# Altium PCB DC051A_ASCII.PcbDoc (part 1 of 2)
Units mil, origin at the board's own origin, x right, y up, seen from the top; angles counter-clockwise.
Board outline 3200 x 2600 mil, 4 copper layers (L1-TOP, L2-GND, L3-POWER, L4-BOTTOM), stack 58.217 mil thick; 95 components, 55 nets, 249 pads, 164 vias.
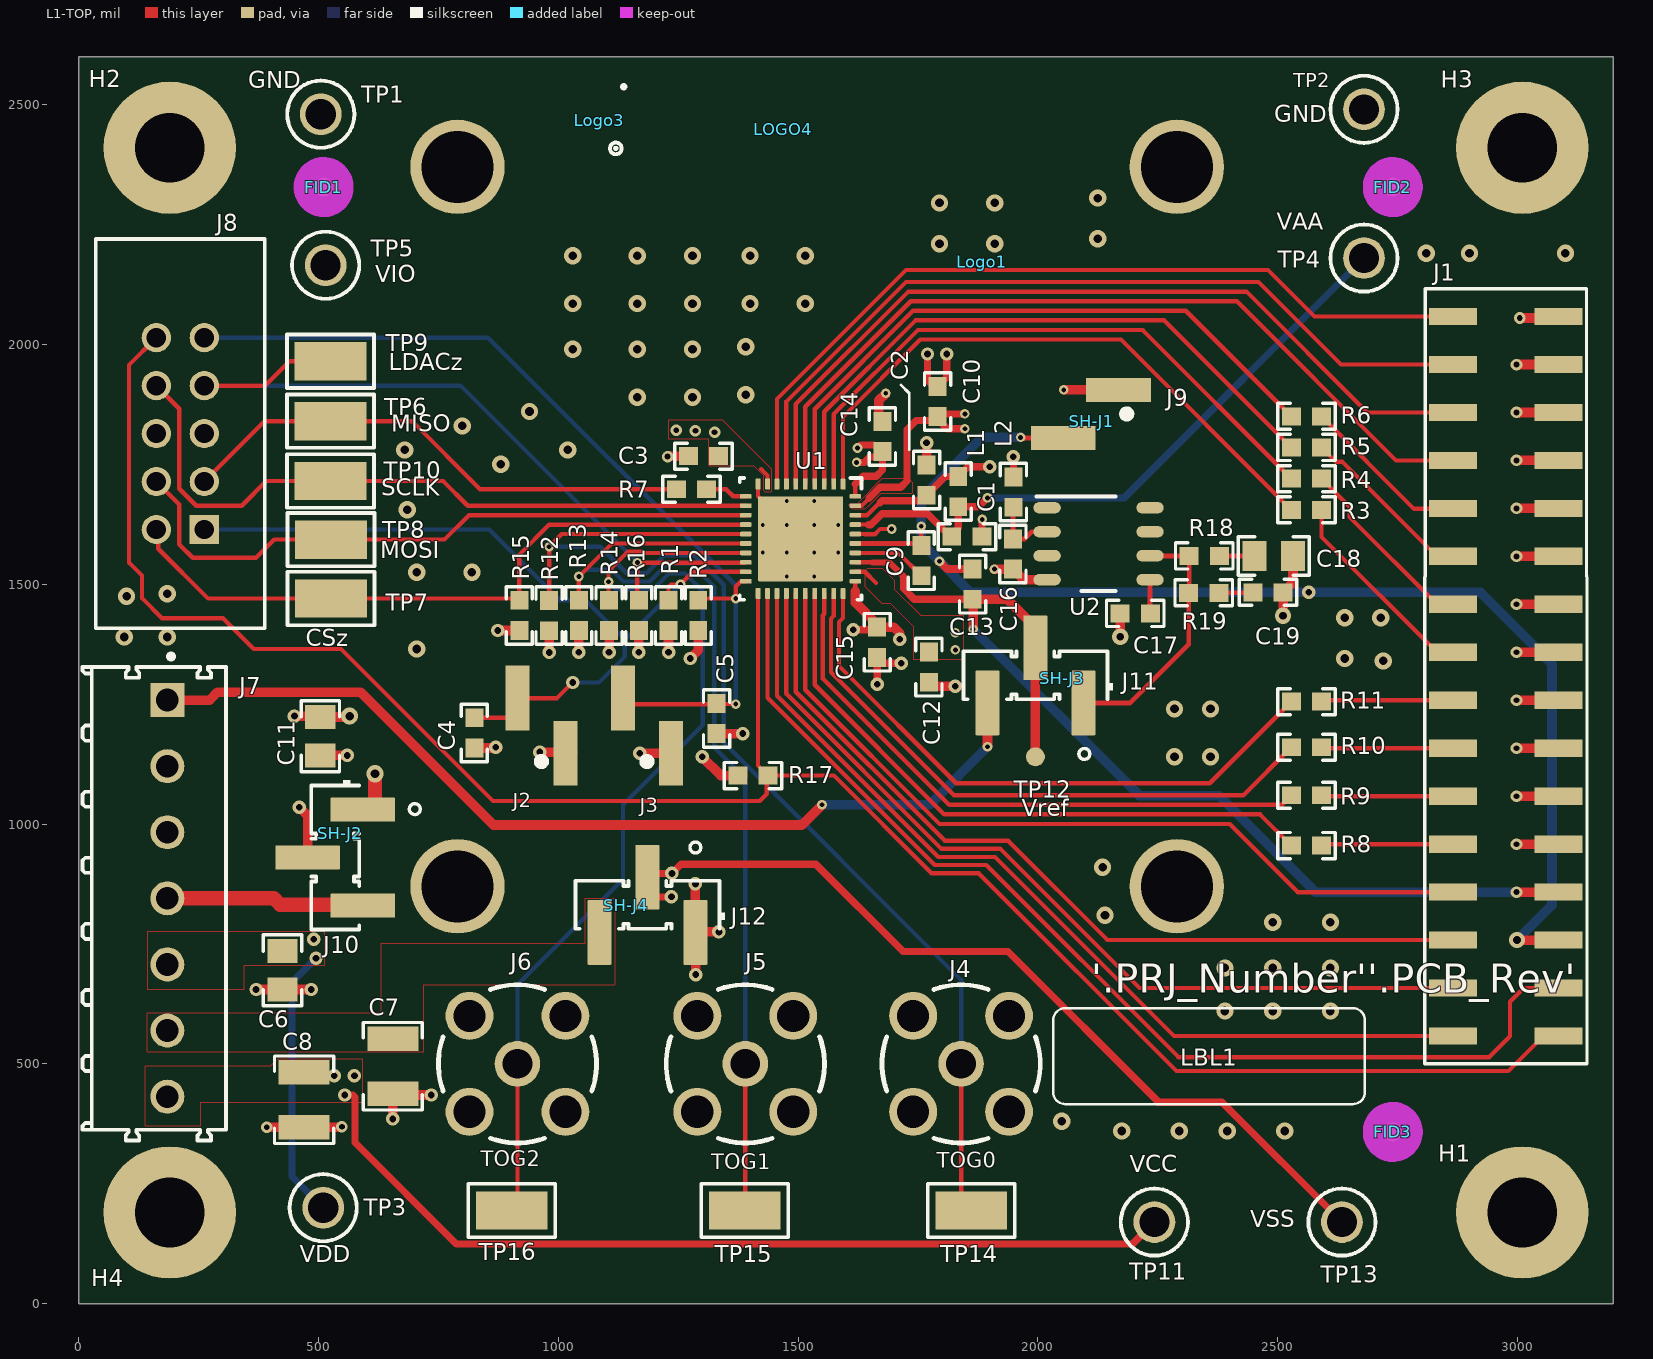
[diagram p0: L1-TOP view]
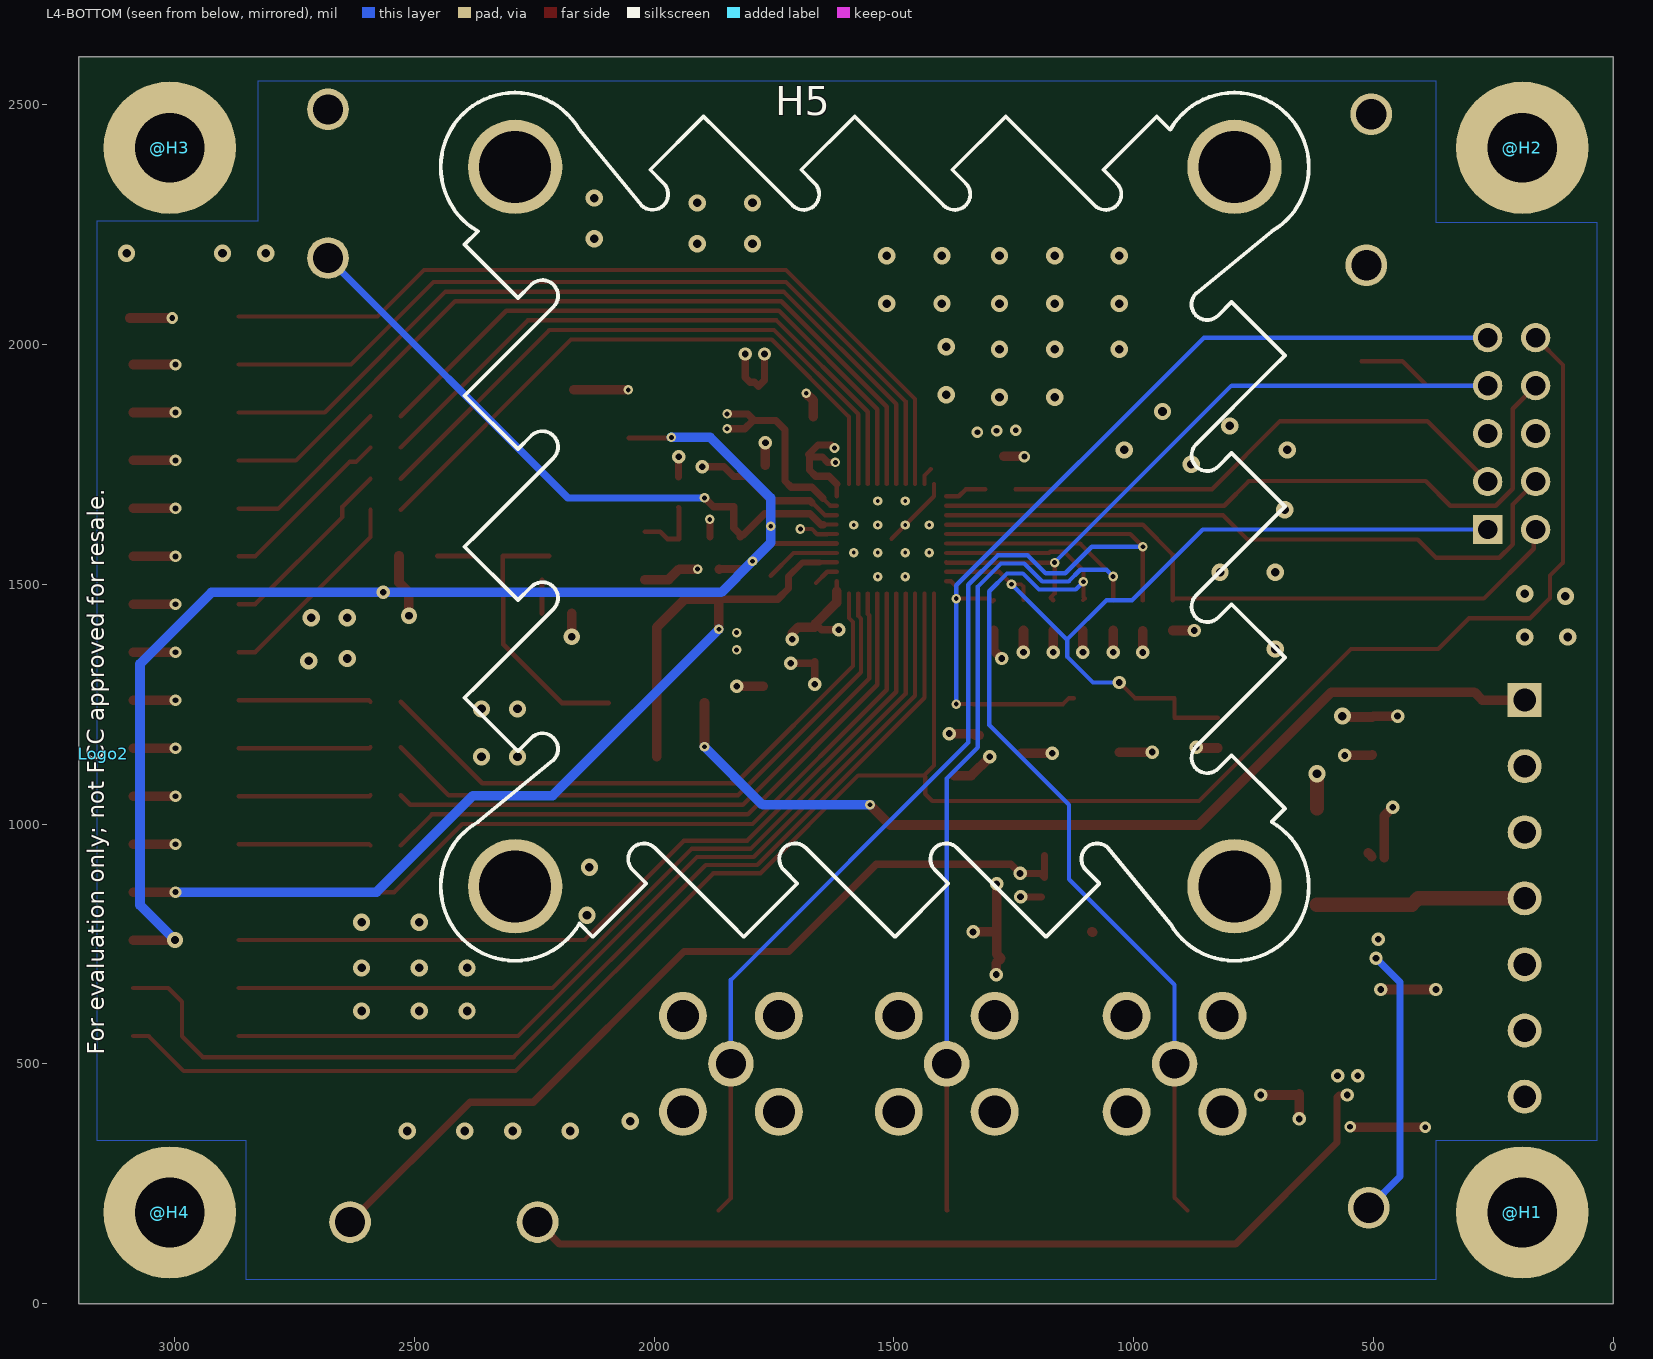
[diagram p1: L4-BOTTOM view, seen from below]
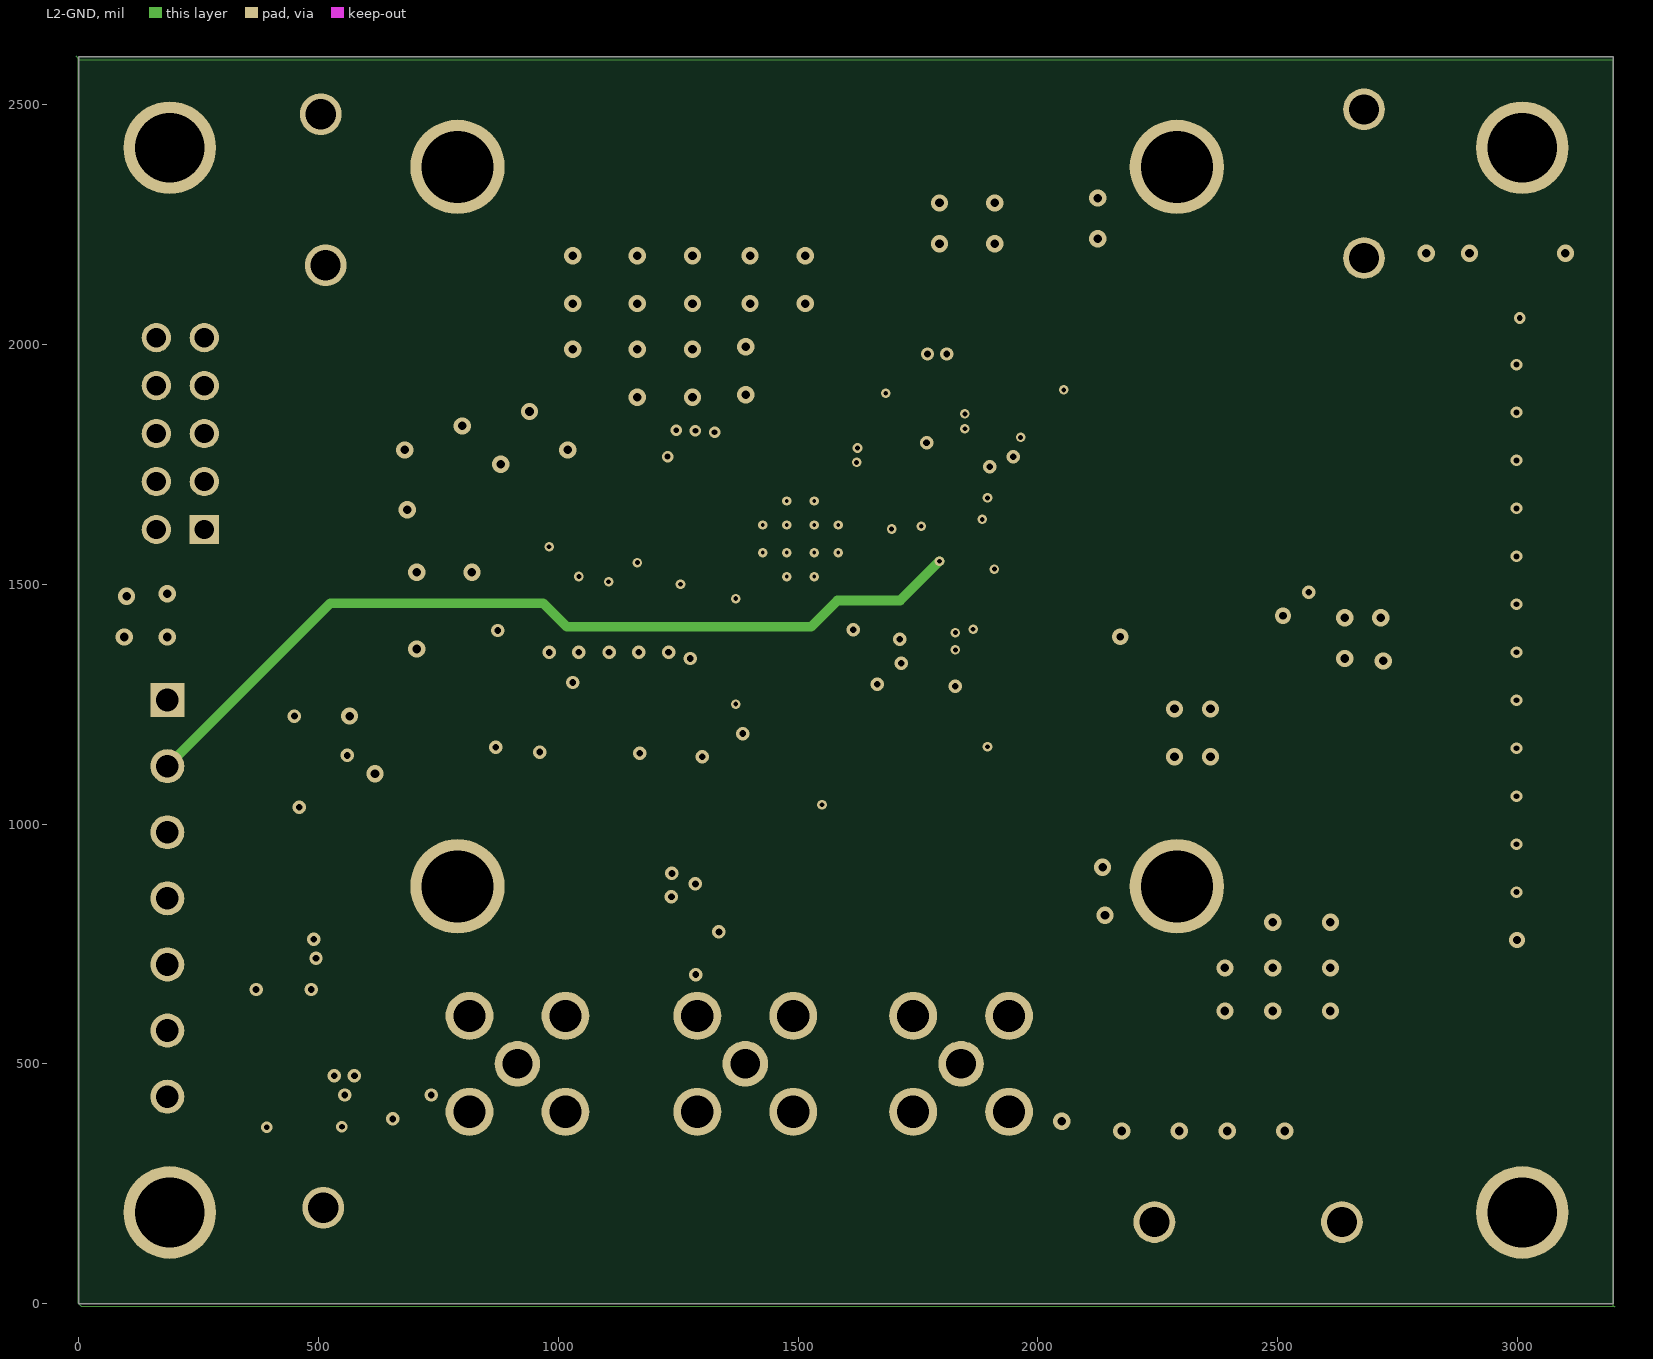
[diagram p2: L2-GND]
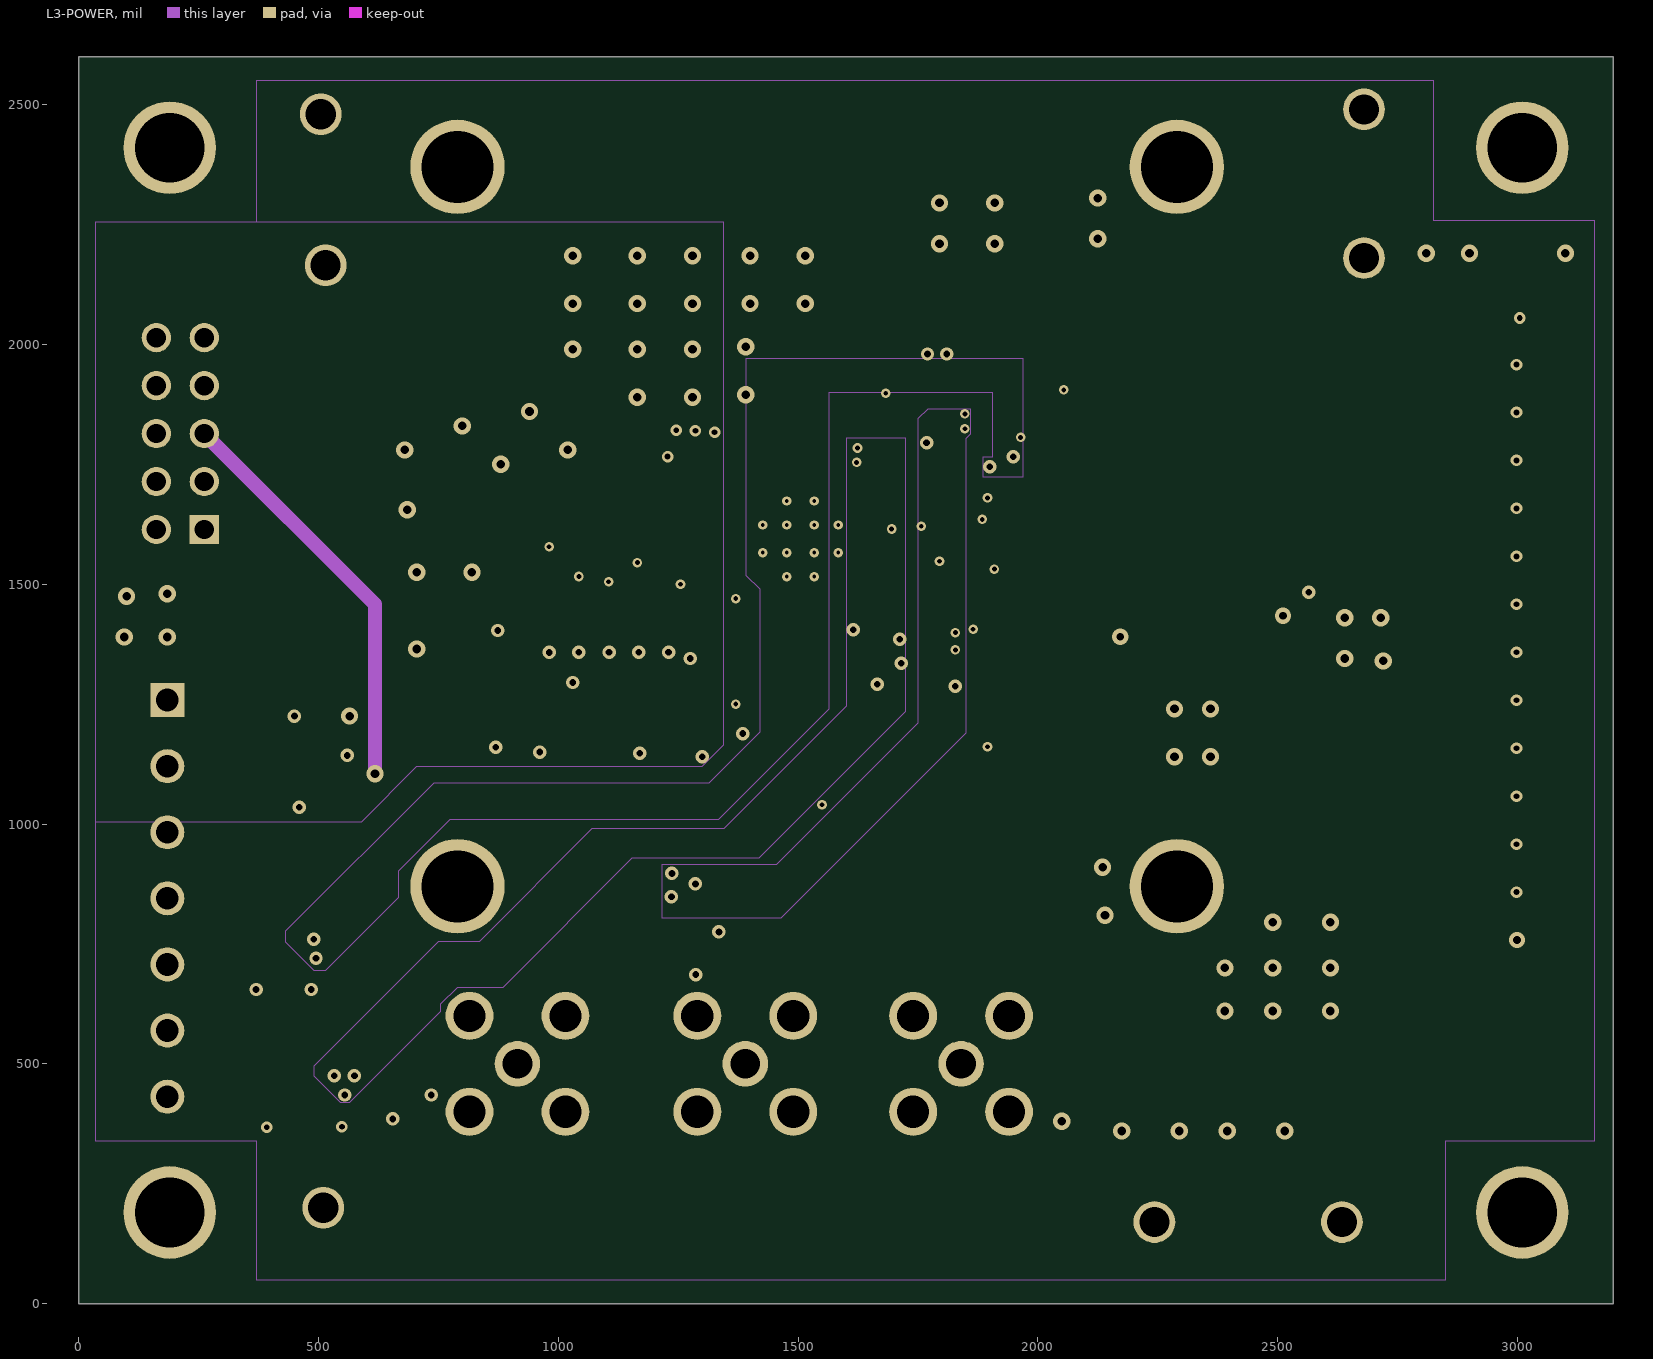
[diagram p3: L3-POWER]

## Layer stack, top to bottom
Top Solder: solder mask 0.4, Solder Resist, Dk 3.5
L1-TOP: signal copper 1.4
Dielectric1: core 10, FR-406, Dk 4.6
L2-GND: signal copper 1.417
Dielectric2: prepreg 32.6, FR-4, Dk 4.8
L3-POWER: signal copper 1.4
Dielectric3: core 10, FR-406, Dk 4.6
L4-BOTTOM: signal copper 1.4
Bottom Solder: solder mask 0.4, Solder Resist, Dk 3.5

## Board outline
0,0 0,2600 3200,2600 3200,0

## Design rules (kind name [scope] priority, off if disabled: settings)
AcuteAngle [All] p0: scope1count=1 scope1_0_kind=Board scope1_0_value=Board scope2count=1 scope2_0_kind=Board scope2_0_value=Board commentlength=0 minimum=4.50000000000000E+0001
AcuteAngle [All] p1: minimum=4.50000000000000E+0001 checktracksonly=FALSE
AssemblyTestPointUsage [All] p0: scope1count=1 scope1_0_kind=Board scope1_0_value=Board scope2count=1 scope2_0_kind=Board scope2_0_value=Board commentlength=0
AssemblyTestPointUsage [All] p1: valid=2
AssemblyTestpoint [All] p0: scope1count=1 scope1_0_kind=Board scope1_0_value=Board scope2count=1 scope2_0_kind=Board scope2_0_value=Board commentlength=0
BoardOutlineClearance [All] p0 off: scope1count=1 scope1_0_kind=Board scope1_0_value=Board scope2count=1 scope2_0_kind=Board scope2_0_value=Board commentlength=172 gap=40 // Protel DXP Scope 1 Expression Was: OnCopper and Not InComponentClass('Logo') and not InComponentClass('FiducialMark') and not InRegion(1000,500,4000,800) and not InPoly
BoardOutlineClearance BoardOutlineClearance_Poly [All] p0 off: scope1count=1 scope1_0_kind=Board scope1_0_value=Board scope2count=1 scope2_0_kind=Board scope2_0_value=Board commentlength=58 gap=25 // Protel DXP Scope 1 Expression Was: OnCopper and IsPoly
BoardOutlineClearance BoardOutlineClearance_MountingHoles [All] p0 off: scope1count=1 scope1_0_kind=Board scope1_0_value=Board scope2count=1 scope2_0_kind=Board scope2_0_value=Board commentlength=86 gap=40 // Protel DXP Scope 1 Expression Was: OnCopper and InComponentClass('Mounting Holes')
BoardOutlineClearance BoardOutlineClearance_MountingHoles [OnCopper and InComponentClass('Mounting Holes')] p1: gap=40 ignorepadtopadclearanceinfootprint=FALSE
BoardOutlineClearance BoardOutlineClearance_Poly [OnCopper and IsPoly] p2: gap=25 ignorepadtopadclearanceinfootprint=FALSE
BoardOutlineClearance [OnCopper and Not InComponentClass('Logo') and not InComponentClass('FiducialMark') and not InRegion(1000,500,4000,800) and not InPoly] p3: gap=40 ignorepadtopadclearanceinfootprint=FALSE
Clearance [All] p0: scope1count=1 scope1_0_kind=Board scope1_0_value=Board scope2count=1 scope2_0_kind=Board scope2_0_value=Board commentlength=0 gap=7.87
Clearance Clearance_Poly [All] p0 off: scope1count=1 scope1_0_kind=Board scope1_0_value=Board scope2count=1 scope2_0_kind=Board scope2_0_value=Board commentlength=48 gap=25 // Protel DXP Scope 1 Expression Was: InPolygon
Clearance Clearance_Keepouts [All] p0 off: scope1count=1 scope1_0_kind=Board scope1_0_value=Board scope2count=1 scope2_0_kind=Board scope2_0_value=Board commentlength=99 gap=0 // Protel DXP Scope 2 Expression Was: ((IsTrack Or IsArc) And Not InPoly) And IsFree and IsKeepOut
Clearance Clearance_Keepouts [((IsTrack Or IsArc) And Not InPoly) And IsFree and IsKeepOut vs ((IsTrack Or IsArc) And Not InPoly) And IsFree and IsKeepOut] p1: gap=0 ignorepadtopadclearanceinfootprint=FALSE
Clearance Clearance_Poly [InPolygon] p2: gap=25 ignorepadtopadclearanceinfootprint=FALSE except(0: Arc-Hole Track-Hole SMDPad-Hole THPad-Hole Via-Hole Fill-Hole Poly-Hole Region-Hole Text-Hole; 10: Poly-Poly; 15: Track-Poly SMDPad-Poly Via-Poly)
Clearance [All] p3: gap=7.87 ignorepadtopadclearanceinfootprint=FALSE except(0: Arc-SMDPad Arc-Hole Track-Hole SMDPad-Hole THPad-Hole Via-Hole Fill-Hole Poly-Hole Region-Hole Text-Hole)
ComponentClearance [All] p0: scope1count=1 scope1_0_kind=Board scope1_0_value=Board scope2count=1 scope2_0_kind=Board scope2_0_value=Board commentlength=0 gap=0 collisioncheckmode=3
ComponentClearance ComponentClearance_THtoTH [All] p0 off: scope1count=1 scope1_0_kind=Board scope1_0_value=Board scope2count=1 scope2_0_kind=Board scope2_0_value=Board commentlength=54 gap=30 collisioncheckmode=3 // Protel DXP Scope 2 Expression Was: IsThruComponent
ComponentClearance ComponentClearance_THtoSMT [All] p0 off: scope1count=1 scope1_0_kind=Board scope1_0_value=Board scope2count=1 scope2_0_kind=Board scope2_0_value=Board commentlength=53 gap=0 collisioncheckmode=3 // Protel DXP Scope 2 Expression Was: IsSMTComponent
ComponentClearance ComponentClearance_SmallPassives [All] p0 off: scope1count=1 scope1_0_kind=Board scope1_0_value=Board scope2count=1 scope2_0_kind=Board scope2_0_value=Board commentlength=542 gap=14.96 collisioncheckmode=3 // Protel DXP Scope 2 Expression Was: HasFootprint('0201*') or HasFootprint('0402*') or HasFootprint('0508') or HasFootprint('0603*') or HasFootprint('0612') or HasFootprint('0805*') or HasFootprint('0815*') or HasFootprint('0830*') or HasFootprint('1206*') or HasFootprint('1210*') or HasFootprint('1808*') or HasFootprint('1812*') or HasFootprint('1825*') or HasFootprint('2010*') or HasFootprint('2220*') or HasFootprint('2225*') or HasFootprint('2512*') or HasFootprint('2728*') or HasFootprint('3518*') or HasFootprint('Keystone_1902C')
ComponentClearance ComponentClearance_MountingHoles [All] p0: scope1count=1 scope1_0_kind=ComponentClass scope1_0_value="Mounting Holes" scope2count=1 scope2_0_kind=Board scope2_0_value=Board commentlength=0 gap=0 collisioncheckmode=3
ComponentClearance ComponentClearance_ScrewToNut [All] p0 off: scope1count=1 scope1_0_kind=Board scope1_0_value=Board scope2count=1 scope2_0_kind=Board scope2_0_value=Board commentlength=71 gap=0 collisioncheckmode=3 // Protel DXP Scope 2 Expression Was: (HasFootprint('Keystone_1902C'))
ComponentClearance ComponentClearance_Logo [All] p0: scope1count=1 scope1_0_kind=ComponentClass scope1_0_value=Logo scope2count=1 scope2_0_kind=Board scope2_0_value=Board commentlength=0 gap=40 collisioncheckmode=3
ComponentClearance ComponentClearance_Shunt [All] p0: scope1count=1 scope1_0_kind=ComponentClass scope1_0_value=Header scope2count=1 scope2_0_kind=ComponentClass scope2_0_value=Shunt commentlength=0 gap=0 collisioncheckmode=3
ComponentClearance ComponentClearance_MountingHoles_FiducialMarks [All] p0: scope1count=1 scope1_0_kind=ComponentClass scope1_0_value="Mounting Holes" scope2count=1 scope2_0_kind=ComponentClass scope2_0_value=FiducialMark commentlength=0 gap=0 collisioncheckmode=3
ComponentClearance ComponentClearance_MountingHoles_FiducialMarks [InComponentClass('Mounting Holes') vs InComponentClass('FiducialMark')] p1: gap=0 collisioncheckmode=3 verticalgap=10 showdistances=FALSE
ComponentClearance ComponentClearance_Shunt [InComponentClass('Header') vs InComponentClass('Shunt')] p2: gap=0 collisioncheckmode=3 verticalgap=0 showdistances=FALSE
ComponentClearance ComponentClearance_Logo [InComponentClass('Logo')] p3: gap=40 collisioncheckmode=3 verticalgap=10 showdistances=FALSE
ComponentClearance ComponentClearance_ScrewToNut [(HasFootprint('NY PMS 440 0025 PH')) vs (HasFootprint('Keystone_1902C'))] p4: gap=0 collisioncheckmode=3 verticalgap=0 showdistances=FALSE
ComponentClearance ComponentClearance_MountingHoles [InComponentClass('Mounting Holes')] p5: gap=0 collisioncheckmode=3 verticalgap=100000 showdistances=FALSE
ComponentClearance ComponentClearance_SmallPassives [HasFootprint('0201*') or HasFootprint('0402*') or HasFootprint('0508') or HasFootprint('0603*') or HasFootprint('0612') or HasFootprint('0805*') or HasFootprint('0815*') or HasFootprint('0830*') or HasFootprint('1206*') or HasFootprint('1210*') or HasFootprint('1808*') or HasFootprint('1812*') or HasFootprint('1825*') or HasFootprint('2010*') or HasFootprint('2220*') or HasFootprint('2225*') or HasFootprint('2512*') or HasFootprint('2728*') or HasFootprint('3518*') or HasFootprint('NY PMS 440 0025 PH') vs HasFootprint('0201*') or HasFootprint('0402*') or HasFootprint('0508') or HasFootprint('0603*') or HasFootprint('0612') or HasFootprint('0805*') or HasFootprint('0815*') or HasFootprint('0830*') or HasFootprint('1206*') or HasFootprint('1210*') or HasFootprint('1808*') or HasFootprint('1812*') or HasFootprint('1825*') or HasFootprint('2010*') or HasFootprint('2220*') or HasFootprint('2225*') or HasFootprint('2512*') or HasFootprint('2728*') or HasFootprint('3518*') or HasFootprint('Keystone_1902C')] p6: gap=14.96 collisioncheckmode=3 verticalgap=10 showdistances=FALSE
ComponentClearance ComponentClearance_THtoSMT [IsThruComponent vs IsSMTComponent] p7: gap=0 collisioncheckmode=3 verticalgap=0 showdistances=FALSE
ComponentClearance ComponentClearance_THtoTH [IsThruComponent vs IsThruComponent] p8: gap=30 collisioncheckmode=3 verticalgap=30 showdistances=FALSE
ComponentClearance [All] p9: gap=0 collisioncheckmode=3 verticalgap=10 showdistances=FALSE
DiffPairsRouting [All] p0: scope1count=1 scope1_0_kind=Board scope1_0_value=Board scope2count=1 scope2_0_kind=Board scope2_0_value=Board commentlength=0
DiffPairsRouting [All] p1: maxlimit=100 minlimit=10 mostfreqgap=10 toplayer_minwidth=15 toplayer_maxwidth=15 toplayer_prefwidth=15 midlayer1_minwidth=15 midlayer1_maxwidth=15 midlayer1_prefwidth=15 midlayer2_minwidth=15 midlayer2_maxwidth=15 midlayer2_prefwidth=15 bottomlayer_minwidth=15 bottomlayer_maxwidth=15 bottomlayer_prefwidth=15 maxuncoupledlength=1000
FabricationTestPointUsage TestPointUsage [All] p0: scope1count=1 scope1_0_kind=Board scope1_0_value=Board scope2count=1 scope2_0_kind=Board scope2_0_value=Board commentlength=0 valid=2 allowmultiple=FALSE
FabricationTestPointUsage TestPointUsage [All] p1: valid=2 allowmultiple=FALSE
FabricationTestpoint Testpoint [All] p0: scope1count=1 scope1_0_kind=Board scope1_0_value=Board scope2count=1 scope2_0_kind=Board scope2_0_value=Board commentlength=0 side=3 testpointundercomponent=TRUE minsize=40 maxsize=100 preferedsize=60 minholesize=0 maxholesize=40 preferedholesize=32 testpointgrid=1
FabricationTestpoint Testpoint [All] p1: side=3 testpointundercomponent=TRUE minsize=40 maxsize=100 preferedsize=60 minholesize=0 maxholesize=40 preferedholesize=32 testpointgrid=1 allowsidetop=TRUE allowsidebottom=TRUE usegrid=TRUE gridtolerance=0.01
FanoutControl Fanout_Small [All] p0 off: scope1count=1 scope1_0_kind=Board scope1_0_value=Board scope2count=1 scope2_0_kind=Board scope2_0_value=Board commentlength=84 // Protel DXP Scope 1 Expression Was: (CompPinCount < 5)   Fanout_Small (Default Rule)
FanoutControl Fanout_Default [All] p0: scope1count=1 scope1_0_kind=Board scope1_0_value=Board scope2count=1 scope2_0_kind=Board scope2_0_value=Board commentlength=30 // Fanout_Default (Default Rule)
FanoutControl Fanout_SOIC [All] p0 off: scope1count=1 scope1_0_kind=Board scope1_0_value=Board scope2count=1 scope2_0_kind=Board scope2_0_value=Board commentlength=71 // Protel DXP Scope 1 Expression Was: IsSOIC   Fanout_SOIC (Default Rule)
FanoutControl Fanout_BGA [All] p0 off: scope1count=1 scope1_0_kind=Board scope1_0_value=Board scope2count=1 scope2_0_kind=Board scope2_0_value=Board commentlength=69 // Protel DXP Scope 1 Expression Was: IsBGA   Fanout_BGA (Default Rule)
FanoutControl Fanout_LCC [All] p0 off: scope1count=1 scope1_0_kind=Board scope1_0_value=Board scope2count=1 scope2_0_kind=Board scope2_0_value=Board commentlength=69 // Protel DXP Scope 1 Expression Was: IsLCC   Fanout_LCC (Default Rule)
FanoutControl Fanout_LCC [IsLCC] p1: bgadir=Out bgaviamode=Centered fanoutstyle=Auto fanoutdirection=Alternating viagrid=1 // Fanout_LCC (Default Rule)
FanoutControl Fanout_BGA [IsBGA] p2: bgadir=Out bgaviamode=Centered fanoutstyle=Auto fanoutdirection=Alternating viagrid=1 // Fanout_BGA (Default Rule)
FanoutControl Fanout_Default [All] p4: bgadir=Out bgaviamode=Centered fanoutstyle=Auto fanoutdirection=Alternating viagrid=1 // Fanout_Default (Default Rule)
FanoutControl Fanout_Small [(CompPinCount < 5)] p5: bgadir=Out bgaviamode=Centered fanoutstyle=Auto fanoutdirection=OutThenIn viagrid=1 // Fanout_Small (Default Rule)
Height [All] p0: scope1count=1 scope1_0_kind=Board scope1_0_value=Board scope2count=1 scope2_0_kind=Board scope2_0_value=Board commentlength=0
Height [All] p1: minheight=0 maxheight=1400 prefheight=500
HoleSize [All] p0: scope1count=1 scope1_0_kind=Board scope1_0_value=Board scope2count=1 scope2_0_kind=Board scope2_0_value=Board commentlength=0 absolutevalues=TRUE maxlimit=251 minlimit=7.87 maxpercent=80.000 minpercent=20.000
HoleSize [All] p1: absolutevalues=TRUE maxlimit=251 minlimit=7.87 maxpercent=80.000 minpercent=20.000
HoleToHoleClearance [All] p0: scope1count=1 scope1_0_kind=Board scope1_0_value=Board scope2count=1 scope2_0_kind=Board scope2_0_value=Board commentlength=0
LayerPairs [All] p0: scope1count=1 scope1_0_kind=Board scope1_0_value=Board scope2count=1 scope2_0_kind=Board scope2_0_value=Board commentlength=0 enforce=TRUE
MinimumAnnularRing [All] p0: scope1count=1 scope1_0_kind=Board scope1_0_value=Board scope2count=1 scope2_0_kind=Board scope2_0_value=Board commentlength=0 minimumring=4
MinimumAnnularRing MinimumAnnularRing_ThermalPadVias [All] p0 off: scope1count=1 scope1_0_kind=Board scope1_0_value=Board scope2count=1 scope2_0_kind=Board scope2_0_value=Board commentlength=63 minimumring=5.91 // Protel DXP Scope 1 Expression Was: IsVia and InAnyComponent
MinimumAnnularRing MinimumAnnularRing_ThermalPadVias [IsVia and InAnyComponent] p1: minimumring=5.91
MinimumAnnularRing [All] p2: minimumring=4
MinimumSolderMaskSliver [All] p0: scope1count=1 scope1_0_kind=Board scope1_0_value=Board scope2count=1 scope2_0_kind=Board scope2_0_value=Board commentlength=0
MinimumSolderMaskSliver MinimumSolderMaskSliver_Logo [All] p0: scope1count=1 scope1_0_kind=ComponentClass scope1_0_value=Logo scope2count=1 scope2_0_kind=ComponentClass scope2_0_value=Logo commentlength=0
MinimumSolderMaskSliver MinimumSolderMaskSliver_Logo [InComponentClass('Logo') vs InComponentClass('Logo')] p1: minsoldermaskwidth=0.7
MinimumSolderMaskSliver [All] p2: minsoldermaskwidth=3.94
NetAntennae [All] p0: scope1count=1 scope1_0_kind=Board scope1_0_value=Board scope2count=1 scope2_0_kind=Board scope2_0_value=Board commentlength=0
PasteMaskExpansion [All] p0: scope1count=1 scope1_0_kind=Board scope1_0_value=Board scope2count=1 scope2_0_kind=Board scope2_0_value=Board commentlength=0 expansion=0
PlaneClearance [All] p0: scope1count=1 scope1_0_kind=Board scope1_0_value=Board scope2count=1 scope2_0_kind=Board scope2_0_value=Board commentlength=0 clearance=20
PlaneConnect [All] p0: scope1count=1 scope1_0_kind=Board scope1_0_value=Board scope2count=1 scope2_0_kind=Board scope2_0_value=Board commentlength=0 planeconnectstyle=Relief reliefexpansion=10 reliefentries=4 reliefconductorwidth=10 reliefairgap=10
PlaneConnect [All] p1: planeconnectstyle=Relief reliefexpansion=10 reliefentries=4 reliefconductorwidth=10 reliefairgap=10
PolygonConnect [All] p0: scope1count=1 scope1_0_kind=Board scope1_0_value=Board scope2count=1 scope2_0_kind=Board scope2_0_value=Board commentlength=0 connectstyle=Direct reliefconductorwidth=10 reliefentries=4 polygonreliefangle="90 Angle"
PolygonConnect [All] p1: connectstyle=Direct reliefconductorwidth=10 reliefentries=4 polygonreliefangle="90 Angle" airgapwidth=10
RoutingCorners [All] p0: scope1count=1 scope1_0_kind=Board scope1_0_value=Board scope2count=1 scope2_0_kind=Board scope2_0_value=Board commentlength=0 cornerstyle=45-Degree minsetback=100 maxsetback=100
RoutingLayers [All] p0: scope1count=1 scope1_0_kind=Board scope1_0_value=Board scope2count=1 scope2_0_kind=Board scope2_0_value=Board commentlength=0 top layer=Automatic mid layer 1=Automatic mid layer 2=Automatic bottom layer=Automatic
RoutingPriority [All] p0: scope1count=1 scope1_0_kind=Board scope1_0_value=Board scope2count=1 scope2_0_kind=Board scope2_0_value=Board commentlength=0
RoutingTopology [All] p0: scope1count=1 scope1_0_kind=Board scope1_0_value=Board scope2count=1 scope2_0_kind=Board scope2_0_value=Board commentlength=0 topology=Shortest
RoutingVias [All] p0: scope1count=1 scope1_0_kind=Board scope1_0_value=Board scope2count=1 scope2_0_kind=Board scope2_0_value=Board commentlength=0 holewidth=16 width=34 viastyle="Through Hole" minholewidth=7.87 minwidth=20 maxholewidth=40 maxwidth=65
RoutingVias ThermalPadVias [All] p0 off: scope1count=1 scope1_0_kind=Board scope1_0_value=Board scope2count=1 scope2_0_kind=Board scope2_0_value=Board commentlength=63 holewidth=7.87 width=19.68 viastyle="Through Hole" minholewidth=7.87 minwidth=19.68 maxholewidth=12.99 maxwidth=23.62 // Protel DXP Scope 1 Expression Was: IsVia and InAnyComponent
RoutingVias ThermalPadVias [IsVia and InAnyComponent] p1: holewidth=7.87 width=19.68 viastyle="Through Hole" minholewidth=7.87 minwidth=19.68 maxholewidth=12.99 maxwidth=23.62
RoutingVias [All] p2: holewidth=16 width=34 viastyle="Through Hole" minholewidth=7.87 minwidth=20 maxholewidth=40 maxwidth=65
ShortCircuit [All] p0: scope1count=1 scope1_0_kind=Board scope1_0_value=Board scope2count=1 scope2_0_kind=Board scope2_0_value=Board commentlength=0 allowed=FALSE
SilkToBoardRegionClearance [All] p0 off: scope1count=1 scope1_0_kind=Board scope1_0_value=Board scope2count=1 scope2_0_kind=Board scope2_0_value=Board commentlength=130 // Protel DXP Scope 1 Expression Was: Not ((IsComment or IsDesignator) And (Hide <> 'False')) and not InRegion(1000,500,4000,800)
SilkToBoardRegionClearance [Not ((IsComment or IsDesignator) And (Hide <> 'False')) and not InRegion(1000,500,4000,800)] p1:
SilkToSilkClearance [All] p0: scope1count=1 scope1_0_kind=Board scope1_0_value=Board scope2count=1 scope2_0_kind=Board scope2_0_value=Board commentlength=0
SilkToSilkClearance SilkToSilkClearance_Pb-FreeLogo [All] p0 off: scope1count=1 scope1_0_kind=Board scope1_0_value=Board scope2count=1 scope2_0_kind=Board scope2_0_value=Board commentlength=120 // Protel DXP Scope 2 Expression Was: (HasFootprint('Pb-Free_Overlay_Medium') OR HasFootprint('Pb-Free_Overlay_Small'))
SilkToSilkClearance SilkToSilkClearance_Pb-FreeLogo [(HasFootprint('Pb-Free_Overlay_Medium') OR HasFootprint('Pb-Free_Overlay_Small')) vs (HasFootprint('Pb-Free_Overlay_Medium') OR HasFootprint('Pb-Free_Overlay_Small'))] p1: silktosilkclearance=0
SilkToSilkClearance [All] p2: silktosilkclearance=3
SilkToSolderMaskClearance "Silk to Solder Mask Opening" [All] p0: scope1count=1 scope1_0_kind=Board scope1_0_value=Board scope2count=1 scope2_0_kind=Board scope2_0_value=Board commentlength=0
SilkToSolderMaskClearance SilkToComponentPadClearance [All] p0 off: scope1count=1 scope1_0_kind=Board scope1_0_value=Board scope2count=1 scope2_0_kind=Board scope2_0_value=Board commentlength=87 // Protel DXP Scope 1 Expression Was: (IsPad or IsFill or IsRegion) and InAnycomponent
SilkToSolderMaskClearance SilkToComponentPadClearance [(IsPad or IsFill or IsRegion) and InAnycomponent] p1: minsilkscreentomaskgap=3 clearancetoexposedcopper=TRUE
SilkToSolderMaskClearance "Silk to Solder Mask Opening" [All] p2: minsilkscreentomaskgap=3 clearancetoexposedcopper=FALSE
SolderMaskExpansion [All] p0: scope1count=1 scope1_0_kind=Board scope1_0_value=Board scope2count=1 scope2_0_kind=Board scope2_0_value=Board commentlength=0 expansion=1.97
SolderMaskExpansion [All] p1: expansion=1.97
UnRoutedNet [All] p0: scope1count=1 scope1_0_kind=Board scope1_0_value=Board scope2count=1 scope2_0_kind=Board scope2_0_value=Board commentlength=0
UnpouredPolygon [All] p0: scope1count=1 scope1_0_kind=Board scope1_0_value=Board scope2count=1 scope2_0_kind=Board scope2_0_value=Board commentlength=0
Width [All] p0: scope1count=1 scope1_0_kind=Board scope1_0_value=Board scope2count=1 scope2_0_kind=Board scope2_0_value=Board commentlength=0 maxlimit=100 minlimit=6 preferedwidth=10
Width [All] p1: maxlimit=100 minlimit=6 preferedwidth=10 checkconnectedcopper=TRUE
14 further rules are at their usual default settings.

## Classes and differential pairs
component class Shunt: SH-J1 SH-J2 SH-J3 SH-J4
component class FiducialMark: FID1 FID2 FID3
component class AssemblyNote: ZZ1 ZZ2 ZZ3 ZZ4
component class Header: J1 J2 J3 J9 J10 J11 J12
component class Logo: Logo1
component class DC051A: C1 C2 C3 C4 C5 C6 C7 C8 C9 C10 C11 C12 C13 C14 C15 C16 C17 C18 C19 GND J1 J2 J3 J4 J5 J6 J7 J8 J9 J10 J11 J12 L1 L2 R1 R2 R3 R4 R5 R6 R7 R8 R9 R10 R11 R12 R13 R14 R15 R16 R17 R18 R19 TP1 TP2 TP3 TP4 TP5 TP6 TP7 TP8 TP9 TP10 TP11 TP12 TP13 TP14 TP15 TP16 U1 U2
component class DC051A_EVM_Hardware: !PCB @H1 @H2 @H3 @H4 FID1 FID2 FID3 H1 H2 H3 H4 H5 LBL1 Logo1 Logo2 Logo3 LOGO4 Logo4 LOGO? Logo? SH-J1 SH-J2 SH-J3 SH-J4 ZZ1 ZZ2 ZZ3 ZZ4
component class Label: LBL1

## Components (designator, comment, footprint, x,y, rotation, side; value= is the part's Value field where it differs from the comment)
@H1 "1891" Keystone_1891 190,190 r180 bottom
@H2 "1891" Keystone_1891 190,2410 r180 bottom
@H3 "1891" Keystone_1891 3010,2410 r180 bottom
@H4 "1891" Keystone_1891 3010,190 r180 bottom
C1 "C0603C105K4PACTU" 0603 1852,1599 r0 top
C2 "C0603C104J4RACTU" 0603 1768,1717 r90 top
C3 "C0603C104J4RACTU" 0603 1303,1767 r180 top
C4 "C0603C105K4PACTU" 0603 825,1190 r270 top
C5 "C0603C105K4PACTU" 0603 1330,1220 r270 top
C6 "GRM21BC8YA106KE11L" 0805_HV 425,695 r270 top
C7 "UMJ325KB7106KMHT" 1210_270 655,495 r270 top
C8 "UMJ325KB7106KMHT" 1210_270 470,425 r270 top
C9 "C0603C102K5RACTU" 0603 1757,1549 r90 top
C10 "C0603C105K4PACTU" 0603 1791,1881 r90 top
C11 "GRM21BC8YA106KE11L" 0805_HV 504,1183 r90 top
C12 "C0603C105K4PACTU" 0603 1773,1327 r270 top
C13 "C0603C104J4RACTU" 0603 1864,1500 r90 top
C14 "C0603C105K4PACTU" 0603 1676,1808 r90 top
C15 "C0603C105K4PACTU" 0603 1665,1379 r270 top
C16 "C1608X5R1E105K080AC" 0603 1948,1563 r270 top
C17 "C1608X5R1E105K080AC" 0603 2203,1439 r180 top
C18 "GRM21BC8YA106KE11L" 0805_HV 2492,1559 r0 top
C19 "C1608X5R1E105K080AC" 0603 2480,1483 r0 top
FID1 "Fiducial" Fiducial10-30 511,2328 r180 top
FID2 "Fiducial" Fiducial10-30 2740,2328 r180 top
FID3 "Fiducial" Fiducial10-30 2740,358 r180 top
H1 "29311" Keystone29311 3010,190 r0 top
H2 "29311" Keystone29311 190,2410 r0 top
H3 "29311" Keystone29311 3010,2410 r0 top
H4 "29311" Keystone29311 190,190 r0 top
H5 "500403B00000G" Aavid_500403B00000G 1540,1620 r0 bottom
J1 "TSM-116-01-T-DV-P" CONN_TSM-116-01-T-DV-P 2976,1308 r90 top
J2 "TSM-102-01-L-SV" Samtec_TSM-102-01-L-SV 965,1205 r180 top
J3 "TSM-102-01-L-SV" Samtec_TSM-102-01-L-SV 1185,1205 r180 top
J4 "142-0701-231" Johnson_142-0701-231 1840,500 r270 top
J5 "142-0701-231" Johnson_142-0701-231 1389.99,500 r180 top
J6 "142-0701-231" Johnson_142-0701-231 915,500 r90 top
J7 "1984662" Phoenix_1984662 185,845 r270 top locked
J8 "AWHW-10G-0202-T" Assman_AWHW-10G-0x02-T 212,1814 r180 top
J9 "TSM-102-01-L-SV" Samtec_TSM-102-01-L-SV 2110.52,1855 r270 top
J10 "TSM-103-01-L-SV-P-TR" Samtec_TSM-103-01-x-SV-P 535,930 r270 top
J11 "TSM-103-01-L-SV-P-TR" Samtec_TSM-103-01-x-SV-P 1995,1310 r180 top
J12 "TSM-103-01-L-SV-P-TR" Samtec_TSM-103-01-x-SV-P 1186,831.5 r180 top
L1 "742792651" 0603 1834,1693 r270 top
L2 "742792651" 0603 1949,1692 r270 top
LBL1 "THT-14-423-10" Label_650x200 2357,516 r0 top
Logo1 "Texas Instruments" TI_Stacked_Overlay_Medium 1883,2172 r0 top
Logo2 "FCC disclaimer" FCC_disclaimer 3149,1146 r90 bottom
Logo3 "WEEE logo" WEEE_Minimum 1086,2467 r0 top
LOGO4 "CE Mark" CE_Mark_5mm 1469,2449 r0 top
R1 "RC0603FR-0710KL" 0603 1230,1435 r270 top
R2 "RC0603FR-0710KL" 0603 1292,1435 r270 top
R3 "RC0603JR-070RL" 0603 2560,1655 r0 top
R4 "RC0603JR-070RL" 0603 2560,1720 r0 top
R5 "RC0603JR-070RL" 0603 2560,1785 r0 top
R6 "RC0603JR-070RL" 0603 2560,1850 r0 top
R7 "CRCW060333R0JNEA" 0603 1278,1698 r0 top
R8 "RC0603JR-070RL" 0603 2560,955 r0 top
R9 "RC0603JR-070RL" 0603 2560,1060 r0 top
R10 "RC0603JR-070RL" 0603 2560,1160 r0 top
R11 "RC0603JR-070RL" 0603 2560,1255 r0 top
R12 "RC0603FR-0710KL" 0603 981,1434.5 r90 top
R13 "RC0603FR-0710KL" 0603 1043,1435 r90 top
R14 "RC0603FR-0710KL" 0603 1106,1435 r90 top
R15 "RC0603FR-0710KL" 0603 919,1435 r90 top
R16 "RC0603FR-0710KL" 0603 1168,1435 r90 top
R17 "RC0603FR-0710KL" 0603 1406,1101 r0 top
R18 "ERJ-3RQFR51V" 0603 2347,1559 r180 top
R19 "RC0603FR-071RL" 0603 2346,1482 r180 top
SH-J1 "SNT-100-BK-G" SNT-100-BK-G 2112,1840 r90 top
SH-J2 "SNT-100-BK-G" SNT-100-BK-G 546,981 r90 top
SH-J3 "SNT-100-BK-G" SNT-100-BK-G 2051,1304 r180 top
SH-J4 "SNT-100-BK-G" SNT-100-BK-G 1142,831 r180 top
TP1 "5005" Keystone5005 505,2480 r270 top
TP2 "5005" Keystone5005 2680,2490 r270 top
TP3 "5005" Keystone5005 510,200 r180 top
TP4 "5005" Keystone5005 2680,2180 r180 top
TP5 "5005" Keystone5005 515,2165 r270 top
TP6 "5019" Keystone_5019 525,1840 r180 top
TP7 "5019" Keystone_5019 526,1470 r0 top
TP8 "5019" Keystone_5019 526,1593 r0 top
TP9 "5019" Keystone_5019 525,1965 r180 top
TP10 "5019" Keystone_5019 525,1715 r180 top
TP11 "5005" Keystone5005 2243,170 r180 top
TP12 "TP_SM_1MM" TP_SM_1MM 1995,1140 r180 top locked
TP13 "5005" Keystone5005 2634,170 r0 top
TP14 "5019" Keystone_5019 1861,194 r180 top
TP15 "5019" Keystone_5019 1389,194 r0 top
TP16 "5019" Keystone_5019 903,194 r0 top
U1 "DAC81416RHA" RHA0040H 1505.28,1594.7 r270 top
U2 "REF5025AIDR" D0008A_N 2126.65,1584.34 r0 top
ZZ1 "Install label in silkscreened box after final wash.  Text shall be 8 pt font.  Text shall be per the Label Table in the PDF schematic." AssemblyNote 218,3663 r0 top
ZZ2 "These assemblies are ESD sensitive, ESD precautions shall be observed." AssemblyNote 218,3570 r0 top
ZZ3 "These assemblies must be clean and free from flux and all contaminants. Use of no clean flux is not acceptable." AssemblyNote 218,3490 r0 top
ZZ4 "These assemblies must comply with workmanship standards IPC-A-610 Class 2, unless otherwise specified." AssemblyNote 218,3402 r0 top

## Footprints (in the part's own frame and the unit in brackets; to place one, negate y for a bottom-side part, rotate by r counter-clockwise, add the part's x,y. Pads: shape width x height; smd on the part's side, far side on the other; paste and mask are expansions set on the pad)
0603 [mm] "0603 from SM-752 data"
  rect 1x0.95 smd: 1(-0.8,0) 2(0.8,0)
  silkscreen extent -1.52,-0.69 1.52,0.69
0805_HV [mil] "0805 with 30mil clearance between pads"
  rect 50x63 smd: 1(-40,0) 2(40,0)
  silkscreen extent -74,-40 74,40
1210_270 [mm] "1210"
  rect 1.3x2.7 smd: 1(-1.45,0) 2(1.45,0)
  silkscreen extent -2.32,-1.57 2.32,1.57
Aavid_500403B00000G [mm] "Heat Sink TO-3 Aluminum"
  round 5 hole 3.81: MH1(-19.05,19.05) MH2(19.05,19.05) MH3(-19.05,-19.05) MH4(19.05,-19.05)
  silkscreen extent -22.99,-22.99 22.99,22.99
AssemblyNote [mil] "Assembly Note"
Assman_AWHW-10G-0x02-T [mm] "Header, 2.54mm, 5x2, TH"
  rect 1.55x1.55 hole 1.02: 1(-1.27,5.08)
  round 1.55 hole 1.02: 2(1.27,5.08) 3(-1.27,2.54) 4(1.27,2.54) 5(-1.27,0) 6(1.27,0) 7(-1.27,-2.54) 8(1.27,-2.54) 9(-1.27,-5.08) 10(1.27,-5.08)
  silkscreen extent -4.47,-10.31 4.47,10.31
CE_Mark_5mm [mil] "Minimum text height for CE Mark"
CONN_TSM-116-01-T-DV-P [mil] "Samtec"
  rect 36x100 smd: 1(-750,-110) 2(-750,110) 3(-650,-110) 4(-650,110) 5(-550,-110) 6(-550,110) 7(-450,-110) 8(-450,110) 9(-350,-110) 10(-350,110) 11(-250,-110) 12(-250,110) 13(-150,-110) 14(-150,110) 15(-50,-110) 16(-50,110) 17(50,-110) 18(50,110) 19(150,-110) 20(150,110) 21(250,-110) 22(250,110) 23(350,-110) 24(350,110) 25(450,-110) 26(450,110) 27(550,-110) 28(550,110) 29(650,-110) 30(650,110) 31(750,-110) 32(750,110)
  silkscreen extent -808,-169 808,169
D0008A_N [mm] "SOIC, 8-Leads, Body 4.9x3.9mm, Pitch 1.27mm, IPC Medium Density"
  oval 1.45x0.6 smd: 1(-2.725,1.905) 2(-2.725,0.635) 3(-2.725,-0.635) 4(-2.725,-1.905) 5(2.725,-1.905) 6(2.725,-0.635) 7(2.725,0.635) 8(2.725,1.905)
  silkscreen extent -3.3,-2.5 0.9,2.5
FCC_disclaimer [mil]
Fiducial10-30 [mm]
  round 1 smd mask+0: 1(0,0)
  L1-TOP keep-out circle w1.678: c0,0 r0.75
Johnson_142-0701-231 [mil] "Johnson Components recommended land pattern"
  round 95 hole 62: 1(0,0)
  round 100 hole 67: 2(100,100) 3(100,-100) 4(-100,-100) 5(-100,100)
  silkscreen extent -165,-165 165,165
Keystone5005 [mil] "Keystone Compact loops"
  round 87 hole 63: 1(0,0)
  silkscreen extent -70,-70 70,70
Keystone29311 [mm] "Srcew, Pan HeadM5x0.5 mm, Zinc Plated  6.0mm L"
  round 7 / inner round 4.9 / far side round 7 hole 3.7: 1(0,0)
Keystone_1891 [mil] "3/16 Hex Female Standoff"
Keystone_5019 [mm] "Test Point, Miniature, SMT"
  rect 3.8x2.03 smd: 1(0,0)
  silkscreen extent -2.31,-1.42 2.31,1.42
Label_650x200 [mil] "Thermal Transfer Label"
  round 1 on Mech13: 0(0,0)
  silkscreen extent -325,-100 325,100
Phoenix_1984662 [mm] "PHOENIX CONTACT"
  rect 1.8x1.8 hole 1.2: 1(-10.5,0)
  round 1.8 hole 1.2: 2(-7,0) 3(-3.5,0) 4(0,0) 5(3.5,0) 6(7,0) 7(10.5,0)
  silkscreen extent -12.82,-4.5 12.82,3.1
RHA0040H [mm] "QFN, 40-Leads, Body 6x6mm, Pitch 0.5mm, Thermal Pad 4.15 x 4.15mm, TI Recommended"
  rrect40% 0.6x0.25 smd: 1(-2.9,2.25) 2(-2.9,1.75) 3(-2.9,1.25) 4(-2.9,0.75) 5(-2.9,0.25) 6(-2.9,-0.25) 7(-2.9,-0.75) 8(-2.9,-1.25) 9(-2.9,-1.75) 10(-2.9,-2.25) 21(2.9,-2.25) 22(2.9,-1.75) 23(2.9,-1.25) 24(2.9,-0.75) 25(2.9,-0.25) 26(2.9,0.25) 27(2.9,0.75) 28(2.9,1.25) 29(2.9,1.75) 30(2.9,2.25)
  rrect40% 0.25x0.6 smd: 11(-2.25,-2.9) 12(-1.75,-2.9) 13(-1.25,-2.9) 14(-0.75,-2.9) 15(-0.25,-2.9) 16(0.25,-2.9) 17(0.75,-2.9) 18(1.25,-2.9) 19(1.75,-2.9) 20(2.25,-2.9) 31(2.25,2.9) 32(1.75,2.9) 33(1.25,2.9) 34(0.75,2.9) 35(0.25,2.9) 36(-0.25,2.9) 37(-0.75,2.9) 38(-1.25,2.9) 39(-1.75,2.9) 40(-2.25,2.9)
  rrect8% 1.26x1.26 on Top Paste: 41(-1.46,1.46) 41(-1.46,0) 41(-1.46,-1.46) 41(0,1.46) 41(0,0) 41(0,-1.46) 41(1.46,1.46) 41(1.46,0) 41(1.46,-1.46)
  rrect2% 4.5x4.5 smd paste-2.5: 41(0,0)
  silkscreen extent -3.22,-3.22 3.22,3.23
Samtec_TSM-102-01-L-SV [mm] "SAMTEC"
  rect 1.27x3.43 smd: 1(-1.27,1.46) 2(1.27,-1.46)
  silkscreen extent -0.2,1.7 0.2,2.1
Samtec_TSM-103-01-x-SV-P [mm] "Header, 2.54mm, 3x1, SMT"
  rrect8% 1.27x3.43 smd: 1(-2.54,1.46) 2(0,-1.46) 3(2.54,1.46)
  silkscreen extent -4.1,-1.27 3.81,1.27
SNT-100-BK-G [mil] "Samtec STEP model"
  round 1 on Mech3: 0(0,0)
TI_Stacked_Overlay_Medium [mil]
TP_SM_1MM [mm] "1mm Test Point, SMT"
  round 1 smd paste-0.5: 1(0,0)
WEEE_Minimum [mil] "WEEElie bin"
  silkscreen extent 22,-71 54,74

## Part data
@H1 @H2 @H3 @H4: library part CMP-0003792-1, "Hex Standoff, #4-40, Aluminum, 1/4\""
C1 C4 C5 C10 C12 C14 C15: library part CMP-0006868-5, "CAP, CERM, 1 uF, 16 V, +/- 10%, X5R, 0603"
C2 C3 C13: library part CMP-0006857-4, "CAP, CERM, 0.1 uF, 16 V, +/- 5%, X7R, 0603"
C6 C11 C18: library part CMP-0008273-1, "CAP, CERM, 10 uF, 35 V, +/- 10%, X6S, 0805"
C7 C8: library part CMP-0009257-2, "CAP, CERM, 10 uF, 50 V, +/- 10%, X7R, AEC-Q200 Grade 1, 1210"
C9: library part CMP-0006847-4, "CAP, CERM, 1000 pF, 50 V, +/- 10%, X7R, 0603"
C16 C17 C19: library part CMP-0007006-5, "CAP, CERM, 1 uF, 25 V, +/- 10%, X5R, 0603"
FID1 FID2 FID3: library part CMP-0077181-1, "Fiducial mark.  There is nothing to buy or mount."
H1 H2 H3 H4: library part CMP-0003639-1, "Screw Pan Head M3"
H5: "Square Basket Heatsink Featuring Slanted Fins"
J1: library part CMP-0075449-1, "Header, 100mil, 16x2, Tin, SMT"
J2 J3 J9: library part CMP-0075467-1, "Header, 100mil, 2x1, Gold with Tin Tail, SMT"
J4 J5 J6: library part CMP-0055820-1, "Connector, SMA, TH"
J7: library part CMP-0055484-1, "TERM BLOCK, 7POS, 3.5MM, TH"
J8: library part CMP-0075161-1, "Header(Shrouded), 2.54mm, 5x2, Gold, TH"
J10 J11 J12: library part CMP-0055592-1, "Header, 2.54mm, 3x1, Gold, SMT"
L1 L2: library part CMP-0003197-2, "Ferrite Bead, 600 ohm @ 100 MHz, 1 A, 0603"
LBL1: library part CMP-0003625-1, "Thermal Transfer Printable Labels, 0.650\" W x 0.200\" H - 10,000 per roll"
Logo1: library part CMP-0074838-1, "Texas Instrument Corporate Signature"
Logo2: library part CMP-0074847-1, "FCC_disclaimer"
Logo3: library part CMP-0074769-1
LOGO4: library part CMP-0074844-1
R1 R2 R12 R13 R14 R15 R16 R17: library part CMP-0022746-3, "RES, 10.0 k, 1%, 0.1 W, 0603"
R3 R4 R5 R6 R8 R9 R10 R11: library part CMP-0025885-3, "RES, 0, 5%, 0.1 W, 0603"
R7: library part CMP-0025787-4, "RES, 33, 5%, 0.1 W, AEC-Q200 Grade 0, 0603"
R18: library part CMP-0022717-2, "RES, 0.51, 1%, 0.1 W, AEC-Q200 Grade 1, 0603"
R19: library part CMP-0022900-2, "RES, 1.00, 1%, 0.1 W, 0603"
SH-J1 SH-J2 SH-J3 SH-J4: library part CMP-0003623-1, "Shunt, 100mil, Gold plated, Black"
TP1 TP2 TP3 TP4 TP5 TP11 TP13: library part CMP-0055142-1, "Test Point, Compact, Red, TH"
TP6 TP7 TP8 TP9 TP10 TP14 TP15 TP16: library part CMP-0055162-1, "Test Point, Miniature, SMT"
TP12: library part CMP-0003825-1, "1mm Test Point, SMT"
U1: library part CMP-0013795-3, "16-Channel, 16-Bit, High-Voltage Output DAC with Precision Internal Reference, RHA0040H (VQFN-40)"
U2: library part CMP-0032581-1, "Low Noise, Very Low Drift, Precision Voltage Reference, -40 to 125 degC, 8-pin SOIC (D), Green (RoHS & no Sb/Br)"
ZZ1 ZZ2 ZZ3 ZZ4: library part CMP-0003615-1

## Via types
v1: diameter 36, hole 18, L1-TOP to L4-BOTTOM, tented both sides, 64 vias
v2: diameter 28, hole 14, L1-TOP to L4-BOTTOM, tented both sides, 41 vias
v3: diameter 20, hole 10, L1-TOP to L4-BOTTOM, tented both sides, 25 vias
v4: diameter 24, hole 12, L1-TOP to L4-BOTTOM, tented both sides, 19 vias
v5: diameter 19.68, hole 7.87, L1-TOP to L4-BOTTOM, 12 vias
v6: diameter 34, hole 16, L1-TOP to L4-BOTTOM, 3 vias

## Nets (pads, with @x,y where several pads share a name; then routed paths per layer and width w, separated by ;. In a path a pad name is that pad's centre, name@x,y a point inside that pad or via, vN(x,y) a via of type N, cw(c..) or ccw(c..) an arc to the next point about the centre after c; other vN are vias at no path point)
ALMOUT_GPIO0: J1.1 J8.10 R17.2 U1.21 | length 4423.3
  L1-TOP w9: J8.10@162,2014 105,1957 105,1545 132,1518 132,1471 174,1429 301,1429 365,1365 547,1365 864,1048 1420,1048 1435,1063 1435,1098.5 R17.2@1437.5,1101 ; U1.21@1416.69,1480.53 1416.69,1121.8 R17.2@1437.5,1101 ; J1.1@3086,558 3054,558 2981,485 2289,485 1876.5,897.5 1778.18,897.5 1574.68,1101 R17.2@1437.5,1101
CLR_GPIO1: C5.1 J3.2 J8.9 R2.1 U1.20 | length 1952
  L1-TOP w8: C5.1@1334.43,1250 v3(1370,1250)
  L1-TOP w9: J3.2@1125,1262.48 J3.2@1135,1262.48 1147.48,1250 C5.1@1334.43,1250 ; R2.1@1292,1466.5 1294.5,1464 1300.5,1470 v3(1370,1470) 1370,1495 1381.12,1506.12 U1.20@1391.1,1506.12
  L4-BOTTOM w9: J8.9@262,2014 853.73,2014 1370,1497.73 v3(1370,1470) v3(1370,1250)
CS_GPIO8: J8.2 R15.2 TP7.1 U1.14 | length 1432.6
  L1-TOP w8: J8.2@162,1614 J8.2@166,1610
  L1-TOP w9: J8.2@166,1610 166,1574 270,1470 TP7.1@526,1470 915.5,1470 R15.2@919,1466.5 919,1562 981.23,1624.23 U1.14@1391.1,1624.23
EXT_REF: J7.1 J11.3 | length 2009.6
  L1-TOP w20: J7.1@185,1245 J7.1@198.39,1258.39 ; J7.1@185,1258.39 J7.1@198.39,1258.39 ; v3(1550,1040) 1508,998 865,998 588,1275 290,1275 273.39,1258.39 J7.1@198.39,1258.39 ; v3(1895,1161) J11.3@1895,1252.52
  L4-BOTTOM w20: v3(1550,1040) 1774,1040 v3(1895,1161)
EXT_VIO: J7.4 J10.3 | length 444.4
  L1-TOP w30: J7.4@185,831.61 198.39,845 407,845 420,832 J10.3@618.5,832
